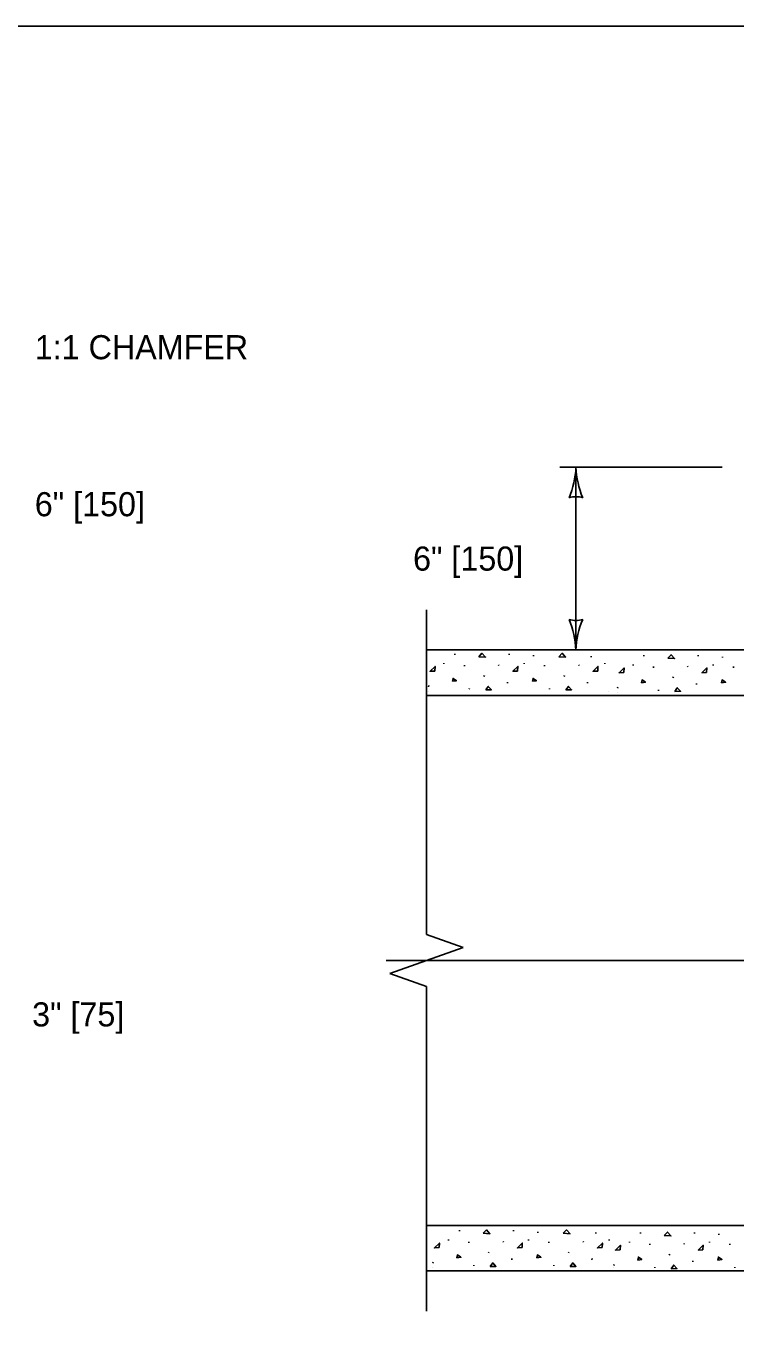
# Model space of a CAD drawing. Extents: x 49991.4 to 50021, y 49987.6 to 50011.4.
# Drawn here: x 50004.383 to 50006.148, y 50008.025 to 50011.263 of the extents above; entities that cross this region are included whole.
import ezdxf

# ---------------------------------------------------------------- set-up
doc = ezdxf.new("R2010")
doc.units = 0
for name, color, linetype in [('Level 1', 7, 'Continuous'), ('Level 2', 7, 'Continuous'), ('Level 3', 7, 'Continuous'), ('Level 5', 7, 'Continuous'), ('Level 6', 7, 'Continuous')]:
    doc.layers.add(name, color=color, linetype=linetype)

msp = doc.modelspace()

# ---------------------------------------------------------------- linework, layer by layer
at = {"layer": 'Level 1'}
for p, q in [((50006.7601, 50009.7099), (50005.3784, 50009.7099)), ((50005.422, 50009.6752), (50005.422, 50009.6774)), ((50005.4493, 50009.6981), (50005.4493, 50009.7007)), ((50005.4726, 50009.6695), (50005.4726, 50009.6721)), ((50005.5587, 50009.6713), (50005.5579, 50009.6731)), ((50005.5842, 50009.6981), (50005.5842, 50009.7007)), ((50005.6212, 50009.6752), (50005.6212, 50009.6774)), ((50005.6442, 50009.6944), (50005.6442, 50009.6968)), ((50005.6718, 50009.6695), (50005.6718, 50009.6721)), ((50005.7578, 50009.6713), (50005.757, 50009.6731)), ((50005.7883, 50009.6922), (50005.7883, 50009.6948)), ((50005.8218, 50009.6752), (50005.8218, 50009.6774)), ((50005.8921, 50009.6716), (50005.8921, 50009.6738)), ((50005.9194, 50009.6945), (50005.9194, 50009.6971)), ((50006.0543, 50009.6945), (50006.0543, 50009.6971)), ((50006.0913, 50009.6716), (50006.0913, 50009.6738)), ((50006.1143, 50009.6908), (50006.1143, 50009.6932)), ((50005.5214, 50009.6443), (50005.5224, 50009.6464)), ((50005.7207, 50009.6443), (50005.7215, 50009.6464)), ((50005.9427, 50009.6659), (50005.9427, 50009.6685)), ((50005.9915, 50009.6407), (50005.9925, 50009.6428)), ((50006.0288, 50009.6677), (50006.028, 50009.6695)), ((50006.1419, 50009.6659), (50006.1419, 50009.6685)), ((50005.3835, 50009.6186), (50005.3841, 50009.6212)), ((50005.3835, 50009.6071), (50005.3835, 50009.6071)), ((50005.485, 50009.6122), (50005.4852, 50009.6142)), ((50005.5796, 50009.6274), (50005.5801, 50009.63)), ((50005.6843, 50009.6122), (50005.6843, 50009.6142)), ((50005.7789, 50009.6274), (50005.7792, 50009.63)), ((50005.832, 50009.6071), (50005.832, 50009.6071)), ((50005.8536, 50009.615), (50005.8542, 50009.6176)), ((50005.9551, 50009.6086), (50005.9553, 50009.6106)), ((50006.0497, 50009.6238), (50006.0502, 50009.6264)), ((50005.3784, 50009.5969), (50006.6011, 50009.5969)), ((50005.8536, 50009.6035), (50005.8536, 50009.6035)), ((50005.3784, 50008.2778), (50006.6011, 50008.2778)), ((50005.4602, 50008.2632), (50005.4602, 50008.2658)), ((50005.5951, 50008.2632), (50005.5951, 50008.2658)), ((50005.6551, 50008.2595), (50005.6551, 50008.2619)), ((50005.7992, 50008.2573), (50005.7992, 50008.2599)), ((50005.9103, 50008.2578), (50005.9103, 50008.2604)), ((50006.0452, 50008.2578), (50006.0452, 50008.2604)), ((50006.1052, 50008.2541), (50006.1052, 50008.2565)), ((50005.4329, 50008.2403), (50005.4329, 50008.2425)), ((50005.4835, 50008.2346), (50005.4835, 50008.2372)), ((50005.5696, 50008.2364), (50005.5688, 50008.2382)), ((50005.6321, 50008.2403), (50005.6321, 50008.2425)), ((50005.6827, 50008.2346), (50005.6827, 50008.2372)), ((50005.7687, 50008.2364), (50005.7679, 50008.2382)), ((50005.8327, 50008.2403), (50005.8327, 50008.2425)), ((50005.883, 50008.2349), (50005.883, 50008.2371)), ((50005.9336, 50008.2292), (50005.9336, 50008.2318)), ((50006.0197, 50008.231), (50006.0189, 50008.2328)), ((50006.0822, 50008.2349), (50006.0822, 50008.2371)), ((50006.1328, 50008.2292), (50006.1328, 50008.2318)), ((50005.3944, 50008.1837), (50005.395, 50008.1863)), ((50005.5323, 50008.2094), (50005.5333, 50008.2115)), ((50005.5905, 50008.1925), (50005.591, 50008.1951)), ((50005.7316, 50008.2094), (50005.7324, 50008.2115)), ((50005.7898, 50008.1925), (50005.7901, 50008.1951)), ((50005.9824, 50008.204), (50005.9834, 50008.2061)), ((50006.0406, 50008.1871), (50006.0411, 50008.1897)), ((50005.3784, 50008.1648), (50006.7601, 50008.1648)), ((50005.3944, 50008.1722), (50005.3944, 50008.1722)), ((50005.4959, 50008.1773), (50005.4961, 50008.1793)), ((50005.6952, 50008.1773), (50005.6952, 50008.1793)), ((50005.8429, 50008.1722), (50005.8429, 50008.1722)), ((50005.8445, 50008.1783), (50005.8451, 50008.1809)), ((50005.8445, 50008.1668), (50005.8445, 50008.1668)), ((50005.946, 50008.1719), (50005.9462, 50008.1739)), ((50006.1453, 50008.1719), (50006.1453, 50008.1739))]:
    msp.add_line(p, q, dxfattribs=at)
for points in [[(50008.6146, 50011.2628), (50000.3356, 50011.2628), (50000.3356, 50000.0624), (50008.6146, 50000.0624)], [(50005.5087, 50009.6932), (50005.5165, 50009.7016), (50005.5254, 50009.6921)], [(50005.7078, 50009.6932), (50005.7159, 50009.7016), (50005.7245, 50009.6921)], [(50005.9788, 50009.6896), (50005.9866, 50009.698), (50005.9955, 50009.6885)], [(50005.3991, 50009.6575), (50005.3997, 50009.6689), (50005.3874, 50009.6568)], [(50005.4429, 50009.632), (50005.453, 50009.6333), (50005.4444, 50009.6391)], [(50005.6051, 50009.6575), (50005.6058, 50009.6689), (50005.5935, 50009.6568)], [(50005.642, 50009.632), (50005.652, 50009.6333), (50005.6435, 50009.6391)], [(50005.8044, 50009.6575), (50005.8049, 50009.6689), (50005.7926, 50009.6568)], [(50005.8692, 50009.6539), (50005.8698, 50009.6653), (50005.8575, 50009.6532)], [(50006.0752, 50009.6539), (50006.0759, 50009.6653), (50006.0636, 50009.6532)], [(50005.5257, 50009.6104), (50005.5322, 50009.6194), (50005.5401, 50009.6108)], [(50005.7247, 50009.6104), (50005.7315, 50009.6194), (50005.7391, 50009.6108)], [(50005.913, 50009.6284), (50005.9231, 50009.6297), (50005.9145, 50009.6355)], [(50005.9958, 50009.6068), (50006.0023, 50009.6158), (50006.0102, 50009.6072)], [(50006.1121, 50009.6284), (50006.1221, 50009.6297), (50006.1136, 50009.6355)], [(50005.5196, 50008.2583), (50005.5274, 50008.2667), (50005.5363, 50008.2572)], [(50005.7187, 50008.2583), (50005.7268, 50008.2667), (50005.7354, 50008.2572)], [(50005.9697, 50008.2529), (50005.9775, 50008.2613), (50005.9864, 50008.2518)], [(50005.41, 50008.2226), (50005.4106, 50008.234), (50005.3983, 50008.2219)], [(50005.616, 50008.2226), (50005.6167, 50008.234), (50005.6044, 50008.2219)], [(50005.8153, 50008.2226), (50005.8158, 50008.234), (50005.8035, 50008.2219)], [(50005.8601, 50008.2172), (50005.8607, 50008.2286), (50005.8484, 50008.2165)], [(50006.0661, 50008.2172), (50006.0668, 50008.2286), (50006.0545, 50008.2165)], [(50005.4538, 50008.1971), (50005.4639, 50008.1984), (50005.4553, 50008.2042)], [(50005.5366, 50008.1755), (50005.5431, 50008.1845), (50005.551, 50008.1759)], [(50005.6529, 50008.1971), (50005.6629, 50008.1984), (50005.6544, 50008.2042)], [(50005.7356, 50008.1755), (50005.7424, 50008.1845), (50005.75, 50008.1759)], [(50005.9039, 50008.1917), (50005.914, 50008.193), (50005.9054, 50008.1988)], [(50006.103, 50008.1917), (50006.113, 50008.193), (50006.1045, 50008.1988)], [(50005.9867, 50008.1701), (50005.9932, 50008.1791), (50006.0011, 50008.1705)]]:
    msp.add_lwpolyline(points, close=True, dxfattribs=at)
at = {"layer": 'Level 3'}
for p, q in [((50006.1141, 50010.1648), (50005.7101, 50010.1648)), ((50005.7501, 50010.1648), (50005.7501, 50009.7099))]:
    msp.add_line(p, q, dxfattribs=at)
for centre, radius, start, end in [((50005.528, 50010.174), 0.2223, 337.456, 357.6395), ((50005.9828, 50010.1763), 0.233, 182.8273, 202.0772), ((50005.7501, 50010.0366), 0.0548, 72.1388, 107.8612), ((50005.7501, 50009.8381), 0.0548, 252.1388, 287.8612), ((50005.5174, 50009.6984), 0.233, 2.8273, 22.0772), ((50005.9722, 50009.7007), 0.2223, 157.456, 177.6395)]:
    msp.add_arc(centre, radius, start, end, dxfattribs=at)
at = {"layer": 'Level 5'}
msp.add_line((50005.2784, 50008.9373), (50007.9685, 50008.9373), dxfattribs=at)
at = {"layer": 'Level 6'}
for p, q in [((50005.3784, 50009.8099), (50005.3784, 50009.0021)), ((50005.4698, 50008.9697), (50005.3784, 50009.0021)), ((50005.4698, 50008.9697), (50005.3784, 50008.9373)), ((50005.3784, 50008.9373), (50005.287, 50008.9049)), ((50005.3784, 50008.8725), (50005.287, 50008.9049)), ((50005.3784, 50008.8725), (50005.3784, 50008.0648))]:
    msp.add_line(p, q, dxfattribs=at)

# ---------------------------------------------------------------- texts
at = {"layer": 'Level 2'}
for s, p in [('1:1 CHAMFER', (50004.4043, 50010.4335)), ('6" [150]', (50004.4043, 50010.0427)), ('6" [150]', (50005.3451, 50009.9074)), ('3" [75]', (50004.3977, 50008.773))]:
    msp.add_text(s, height=0.06, dxfattribs=at).set_placement(p)

doc.saveas('drawing.dxf')
